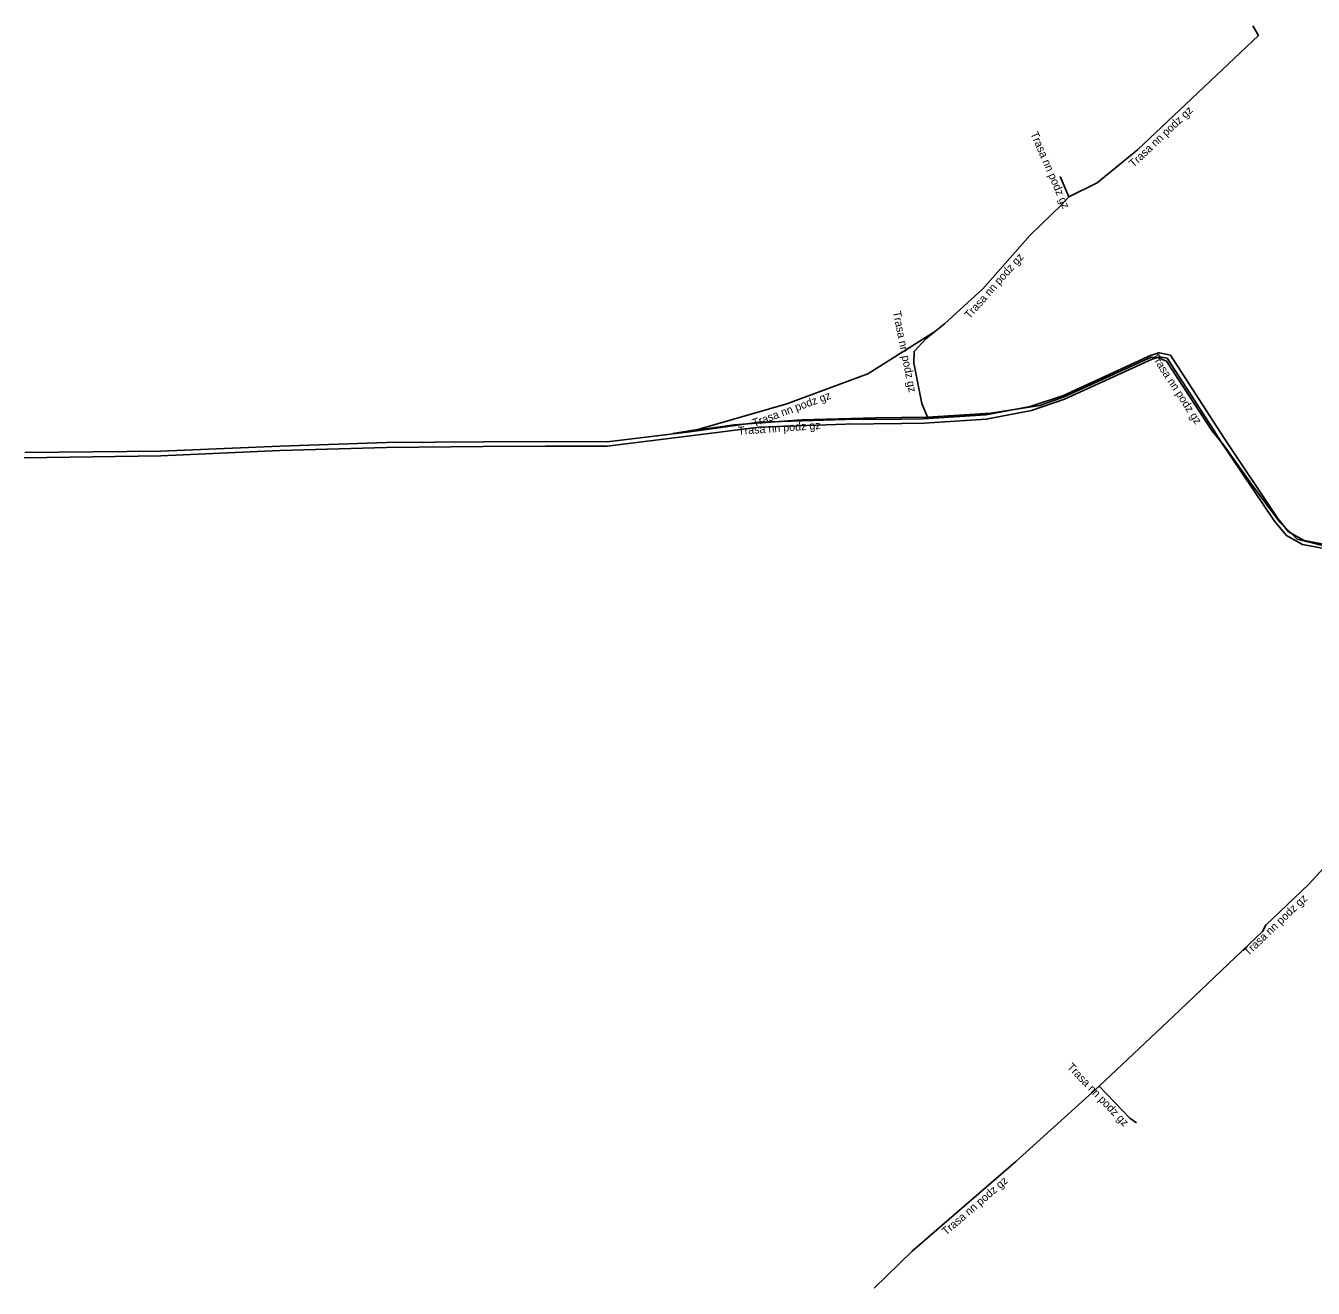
# Model space of a CAD drawing. Extents: x -746106 to -745701, y -1027695 to -1027301.
# Drawn here: x -745938.8 to -745858.4, y -1027601.2 to -1027522.4 of the extents above; entities that cross this region are included whole.
import ezdxf

# ---------------------------------------------------------------- set-up
doc = ezdxf.new("R2010")
doc.units = 0
for name, color, linetype in [('Popiskový text - Ostatní atributy Trasy', 7, 'Continuous'), ('Spojnice NN', 7, 'Continuous'), ('Spojnice VN', 7, 'Continuous')]:
    doc.layers.add(name, color=color, linetype=linetype)

msp = doc.modelspace()

# ---------------------------------------------------------------- linework, layer by layer
at = {"layer": 'Spojnice NN'}
for points in [[(-745873.64, -1027533.05), (-745871.86, -1027532.18), (-745869.34, -1027530.11), (-745866.73, -1027527.64), (-745861.79, -1027522.98), (-745862.134, -1027522.361)], [(-745873.64, -1027533.05), (-745874.18, -1027531.79)], [(-745882.03, -1027541.49), (-745881.41, -1027540.99), (-745879.01, -1027538.79), (-745876.05, -1027535.44), (-745874.1, -1027533.56), (-745873.64, -1027533.05)], [(-745882.03, -1027541.49), (-745886.19, -1027544.12), (-745891.25, -1027545.99), (-745896.81, -1027547.59), (-745898.38, -1027547.845)], [(-745882.46, -1027546.81), (-745882.83, -1027545.97), (-745883.33, -1027543.45), (-745883.31, -1027542.71), (-745882.57, -1027541.93), (-745882.03, -1027541.49)], [(-745853.61, -1027553.12), (-745855.35, -1027552.67), (-745856.03, -1027555.3), (-745856.34, -1027555.24), (-745857.62, -1027554.88), (-745859.38, -1027554.44), (-745860.45, -1027553.37), (-745862.22, -1027551.01), (-745863.97, -1027548.54), (-745864.71, -1027547.66), (-745867.54, -1027543.32), (-745868.03, -1027543.12), (-745868.49, -1027543.06), (-745873.93, -1027545.55), (-745875.45, -1027546.09), (-745878.52, -1027546.57), (-745882.46, -1027546.81)], [(-745882.46, -1027546.81), (-745885.72, -1027546.86), (-745890.32, -1027546.99), (-745894.55, -1027547.29), (-745898.38, -1027547.845)], [(-745854.18, -1027562.73), (-745855.6, -1027569.32), (-745856.75, -1027573.94), (-745858.67, -1027576.02), (-745861.33, -1027578.57), (-745861.54, -1027578.95), (-745867.09, -1027584.25), (-745871.75, -1027588.63)], [(-745871.75, -1027588.63), (-745876.94, -1027593.34), (-745883.42, -1027598.94), (-745885.8, -1027601.25)], [(-745871.75, -1027588.63), (-745869.82, -1027590.63), (-745869.4, -1027590.91)]]:
    msp.add_lwpolyline(points, dxfattribs=at)
at = {"layer": 'Spojnice VN'}
for points in [[(-745938.872, -1027549.032), (-745930.372, -1027548.943), (-745922.907, -1027548.625), (-745916.263, -1027548.397), (-745910.194, -1027548.359), (-745906.329, -1027548.346), (-745902.481, -1027548.359), (-745897.31, -1027547.736), (-745893.001, -1027547.139), (-745887.602, -1027546.974), (-745884.111, -1027546.936), (-745882.729, -1027546.923), (-745878.814, -1027546.669), (-745876.056, -1027546.155), (-745873.97, -1027545.456), (-745868.494, -1027542.943), (-745867.965, -1027542.796), (-745867.289, -1027542.952), (-745864.391, -1027547.425), (-745863.9, -1027548.198), (-745860.574, -1027553.145), (-745859.906, -1027553.992), (-745858.941, -1027554.526), (-745857.038, -1027554.881)], [(-745938.897, -1027549.354), (-745930.363, -1027549.238), (-745922.938, -1027548.898), (-745916.256, -1027548.716), (-745910.23, -1027548.656), (-745906.324, -1027548.625), (-745902.484, -1027548.63), (-745897.304, -1027547.994), (-745892.989, -1027547.449), (-745887.598, -1027547.258), (-745884.066, -1027547.218), (-745882.668, -1027547.198), (-745878.794, -1027546.946), (-745875.963, -1027546.412), (-745873.91, -1027545.704), (-745868.432, -1027543.185), (-745867.978, -1027543.047), (-745867.5, -1027543.127), (-745864.615, -1027547.567), (-745864.137, -1027548.35), (-745860.797, -1027553.311), (-745860.031, -1027554.216), (-745859.035, -1027554.774), (-745857.13, -1027555.14)]]:
    msp.add_lwpolyline(points, dxfattribs=at)

# ---------------------------------------------------------------- texts
at = {"layer": 'Popiskový text - Ostatní atributy Trasy'}
for rotation, p in [(43.42138, (-745869.596, -1027531.248)), (293.19859, (-745876.042, -1027529.098)), (48.53676, (-745879.839, -1027540.709)), (281.22246, (-745884.63, -1027540.235)), (303.10731, (-745868.531, -1027542.99)), (20.28256, (-745893.299, -1027547.44)), (4.05674, (-745894.282, -1027547.923)), (43.79048, (-745862.423, -1027580.518)), (313.97957, (-745873.782, -1027587.461)), (40.8335, (-745881.305, -1027597.971))]:
    msp.add_text('Trasa nn podz gz', height=0.5, rotation=rotation, dxfattribs=at).set_placement(p)

doc.saveas('drawing.dxf')
